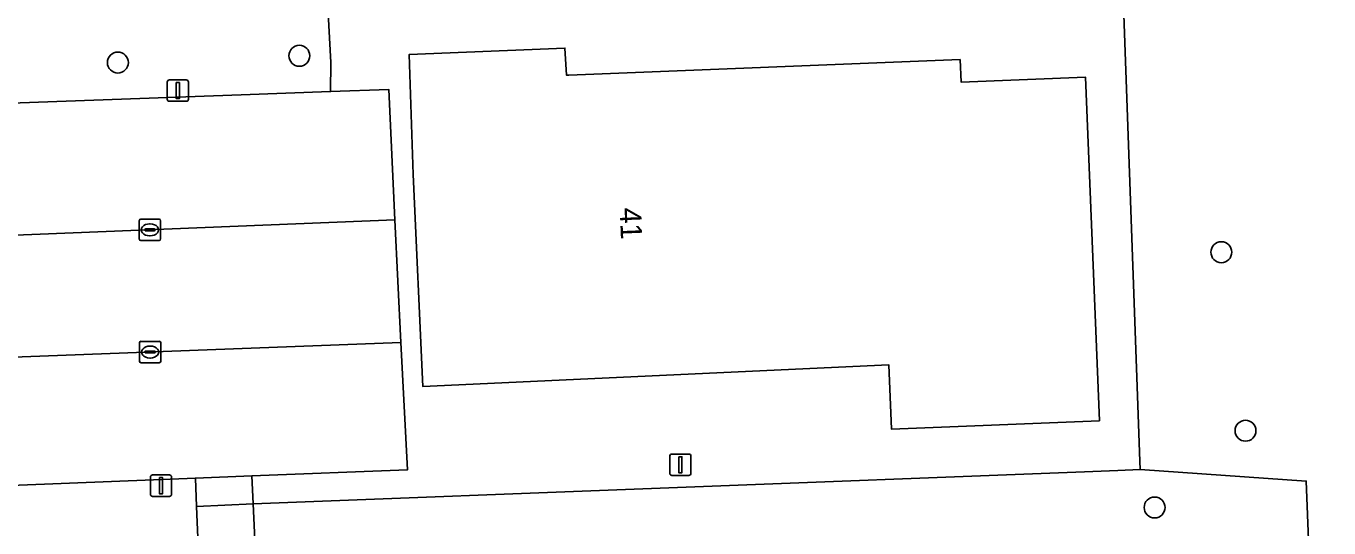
# Model space of a CAD drawing. Extents: x 162510 to 163918, y 388494 to 389774.
# Drawn here: x 162603.2 to 162664.2, y 388722 to 388745.4 of the extents above; entities that cross this region are included whole.
import ezdxf

# ---------------------------------------------------------------- set-up
doc = ezdxf.new("R2010")
doc.units = 0
for name, color, linetype in [('IMGEO_Boom', 7, 'Continuous'), ('IMGEO_Groenvoorziening', 7, 'Continuous'), ('IMGEO_Hek', 7, 'Continuous'), ('IMGEO_Kolk', 7, 'Continuous'), ('IMGEO_Lichtmast', 7, 'Continuous'), ('IMGEO_Pand', 7, 'Continuous'), ('IMGEO_Pand_nummerreeks', 7, 'Continuous'), ('IMGEO_Parkeervlak_open', 7, 'Continuous'), ('IMGEO_Voetpad_open', 7, 'Continuous')]:
    doc.layers.add(name, color=color, linetype=linetype)

msp = doc.modelspace()

# ---------------------------------------------------------------- linework, layer by layer
at = {"layer": 'IMGEO_Boom'}
for centre in [(162607.538, 388743.725), (162616.024, 388744.043), (162659.135, 388734.868), (162660.266, 388726.53), (162656.015, 388722.946)]:
    msp.add_circle(centre, 0.489, dxfattribs=at)
at = {"layer": 'IMGEO_Groenvoorziening'}
for points in [[(162570.603, 388903.112), (162575.652, 388750), (162576.205, 388733.677), (162576.423, 388733.739), (162576.634, 388733.821), (162576.837, 388733.921), (162577.03, 388734.039), (162577.212, 388734.174), (162577.381, 388734.324), (162577.536, 388734.489), (162577.66, 388734.646), (162577.999, 388735.283), (162577.741, 388740.923), (162577.5, 388746.093), (162578.716, 388746.131), (162579.502, 388746.156), (162579.691, 388740.996), (162613.301, 388742.225), (162617.482, 388742.368), (162617.493, 388743.727), (162617.26, 388748.066), (162576.503, 388746.666), (162571.458, 388901.227)], [(162672.289, 388823.443), (162675.321, 388750.649), (162654.434, 388749.809), (162654.518, 388747.72), (162655.329, 388725.102), (162655.344, 388724.714), (162663.108, 388724.176), (162663.228, 388721.043), (162672.068, 388721.393), (162672.037, 388721.095), (162692.862, 388721.935), (162693.526, 388721.762), (162693.788, 388721.694), (162698.73, 388720.407)]]:
    msp.add_lwpolyline(points, dxfattribs=at)
for points in [[(162611.219, 388722.999), (162611.166, 388724.317), (162578.56, 388723.023), (162578.31, 388727.925), (162577.395, 388728.281), (162576.389, 388728.377), (162577.766, 388721.486), (162578.525, 388717.688), (162578.613, 388717.246), (162578.636, 388716.894), (162581.582, 388716.929), (162584.933, 388716.929), (162611.423, 388717.95), (162611.381, 388718.989)], [(162655.344, 388724.714), (162654.289, 388724.673), (162652.74, 388724.613), (162613.863, 388723.119), (162614.044, 388719.095), (162652.876, 388720.633), (162654.987, 388720.717), (162663.228, 388721.043), (162663.108, 388724.176)]]:
    msp.add_lwpolyline(points, close=True, dxfattribs=at)
at = {"layer": 'IMGEO_Hek'}
for points in [[(162652.74, 388724.613), (162613.863, 388723.119)], [(162654.289, 388724.673), (162652.74, 388724.613)], [(162655.344, 388724.714), (162654.289, 388724.673)]]:
    msp.add_lwpolyline(points, dxfattribs=at)
at = {"layer": 'IMGEO_Kolk'}
for p, q in [((162608.536, 388735.485), (162608.536, 388736.337)), ((162608.611, 388736.411), (162609.463, 388736.411)), ((162609.024, 388736.191), (162609.049, 388736.191)), ((162609.537, 388736.337), (162609.537, 388735.485)), ((162608.795, 388735.905), (162608.795, 388735.917)), ((162609.233, 388735.868), (162608.835, 388735.868)), ((162608.838, 388735.954), (162609.236, 388735.954)), ((162609.047, 388735.631), (162609.022, 388735.631)), ((162609.279, 388735.917), (162609.279, 388735.905)), ((162609.463, 388735.411), (162608.611, 388735.411)), ((162608.621, 388730.705), (162609.473, 388730.705)), ((162608.546, 388729.779), (162608.546, 388730.631)), ((162608.805, 388730.199), (162608.805, 388730.211)), ((162609.243, 388730.162), (162608.845, 388730.162)), ((162608.848, 388730.248), (162609.246, 388730.248)), ((162609.034, 388730.485), (162609.059, 388730.485)), ((162609.289, 388730.211), (162609.289, 388730.199)), ((162609.547, 388730.631), (162609.547, 388729.779)), ((162609.473, 388729.705), (162608.621, 388729.705)), ((162609.057, 388729.925), (162609.032, 388729.925))]:
    msp.add_line(p, q, dxfattribs=at)
for points in [[(162608.536, 388735.485), (162608.536, 388736.337)], [(162608.611, 388736.411), (162609.463, 388736.411)], [(162609.537, 388736.337), (162609.537, 388735.485)], [(162609.463, 388735.411), (162608.611, 388735.411)], [(162608.621, 388730.705), (162609.473, 388730.705)], [(162608.546, 388729.779), (162608.546, 388730.631)], [(162609.547, 388730.631), (162609.547, 388729.779)], [(162609.473, 388729.705), (162608.621, 388729.705)]]:
    msp.add_lwpolyline(points, dxfattribs=at)
for centre, radius, start, end in [((162608.613, 388736.335), 0.0765, 91.55205, 178.44795), ((162608.613, 388736.335), 0.0765, 91.55205, 178.44795), ((162609.461, 388736.335), 0.0765, 1.55205, 88.44795), ((162609.461, 388736.335), 0.0765, 1.55205, 88.44795), ((162608.835, 388735.914), 0.0403, 85.87752, 175.75265), ((162608.832, 388735.904), 0.0366, 178.93798, 274.71019), ((162609.236, 388735.911), 0.043, 264.86636, 352.45326), ((162609.24, 388735.916), 0.0386, 1.73085, 96.63898), ((162608.613, 388735.487), 0.0765, 181.55205, 268.44795), ((162608.613, 388735.487), 0.0765, 181.55205, 268.44795), ((162609.461, 388735.487), 0.0765, 271.55205, 358.44795), ((162609.461, 388735.487), 0.0765, 271.55205, 358.44795), ((162608.623, 388730.629), 0.0765, 91.55205, 178.44795), ((162608.623, 388730.629), 0.0765, 91.55205, 178.44795), ((162609.471, 388730.629), 0.0765, 1.55205, 88.44795), ((162609.471, 388730.629), 0.0765, 1.55205, 88.44795), ((162608.845, 388730.208), 0.0403, 85.87752, 175.75265), ((162608.842, 388730.198), 0.0366, 178.93798, 274.71019), ((162609.246, 388730.205), 0.043, 264.86636, 352.45326), ((162609.25, 388730.21), 0.0386, 1.73085, 96.63898), ((162608.623, 388729.781), 0.0765, 181.55205, 268.44795), ((162608.623, 388729.781), 0.0765, 181.55205, 268.44795), ((162609.471, 388729.781), 0.0765, 271.55205, 358.44795), ((162609.471, 388729.781), 0.0765, 271.55205, 358.44795)]:
    msp.add_arc(centre, radius, start, end, dxfattribs=at)
for centre, major_axis, ratio, start_param, end_param in [((162609.023, 388735.911), (-0.387, 0.002), 0.722429, 4.712389, 7.853982), ((162609.048, 388735.911), (-0.39, 0.002), 0.717154, 1.570796, 4.712389), ((162609.033, 388730.205), (-0.387, 0.002), 0.722429, 4.712389, 7.853982), ((162609.058, 388730.205), (-0.39, 0.002), 0.717154, 1.570796, 4.712389)]:
    msp.add_ellipse(centre, major_axis=major_axis, ratio=ratio, start_param=start_param, end_param=end_param, dxfattribs=at)
at = {"layer": 'IMGEO_Lichtmast'}
for p, q in [((162609.945, 388742.915), (162610.735, 388742.915)), ((162610.735, 388742.915), (162609.945, 388742.915)), ((162609.845, 388742.015), (162609.845, 388742.815)), ((162609.845, 388742.815), (162609.845, 388742.015)), ((162610.835, 388742.815), (162610.835, 388742.015)), ((162610.835, 388742.015), (162610.835, 388742.815)), ((162610.735, 388741.915), (162609.945, 388741.915)), ((162609.945, 388741.915), (162610.735, 388741.915)), ((162633.345, 388724.542), (162633.345, 388725.342)), ((162633.345, 388725.342), (162633.345, 388724.542)), ((162633.445, 388725.442), (162634.235, 388725.442)), ((162634.235, 388725.442), (162633.445, 388725.442)), ((162634.335, 388725.342), (162634.335, 388724.542)), ((162634.335, 388724.542), (162634.335, 388725.342)), ((162609.061, 388723.564), (162609.061, 388724.364)), ((162609.061, 388724.364), (162609.061, 388723.564)), ((162609.161, 388724.464), (162609.951, 388724.464)), ((162609.951, 388724.464), (162609.161, 388724.464)), ((162610.051, 388724.364), (162610.051, 388723.564)), ((162610.051, 388723.564), (162610.051, 388724.364)), ((162634.235, 388724.442), (162633.445, 388724.442)), ((162633.445, 388724.442), (162634.235, 388724.442)), ((162609.951, 388723.464), (162609.161, 388723.464)), ((162609.161, 388723.464), (162609.951, 388723.464))]:
    msp.add_line(p, q, dxfattribs=at)
for points in [[(162610.265, 388742.79), (162610.415, 388742.79), (162610.415, 388742.04), (162610.265, 388742.04), (162610.265, 388742.79)], [(162633.765, 388725.317), (162633.915, 388725.317), (162633.915, 388724.567), (162633.765, 388724.567), (162633.765, 388725.317)], [(162609.481, 388724.339), (162609.631, 388724.339), (162609.631, 388723.589), (162609.481, 388723.589), (162609.481, 388724.339)]]:
    msp.add_lwpolyline(points, dxfattribs=at)
for centre, start, end in [((162609.945, 388742.815), 90, 180), ((162609.945, 388742.815), 90, 180), ((162610.735, 388742.815), 0, 90), ((162610.735, 388742.815), 360, 90), ((162609.945, 388742.015), 180, 270), ((162609.945, 388742.015), 180, 270), ((162610.735, 388742.015), 270, 0), ((162610.735, 388742.015), 270, 0), ((162633.445, 388725.342), 90, 180), ((162633.445, 388725.342), 90, 180), ((162634.235, 388725.342), 0, 90), ((162634.235, 388725.342), 360, 90), ((162609.161, 388724.364), 90, 180), ((162609.161, 388724.364), 90, 180), ((162609.951, 388724.364), 0, 90), ((162609.951, 388724.364), 360, 90), ((162633.445, 388724.542), 180, 270), ((162633.445, 388724.542), 180, 270), ((162634.235, 388724.542), 270, 0), ((162634.235, 388724.542), 270, 0), ((162609.161, 388723.564), 180, 270), ((162609.161, 388723.564), 180, 270), ((162609.951, 388723.564), 270, 0), ((162609.951, 388723.564), 270, 0)]:
    msp.add_arc(centre, 0.1, start, end, dxfattribs=at)
at = {"layer": 'IMGEO_Pand'}
msp.add_lwpolyline([(162646.92, 388743.867), (162628.632, 388743.136), (162628.518, 388743.131), (162628.439, 388744.399), (162621.162, 388744.102), (162621.353, 388738.494), (162621.796, 388728.603), (162643.587, 388729.613), (162643.707, 388726.604), (162653.435, 388726.995), (162652.778, 388743.049), (162646.964, 388742.816)], close=True, dxfattribs=at)
at = {"layer": 'IMGEO_Parkeervlak_open'}
for points in [[(162620.203, 388742.474), (162617.482, 388742.368), (162613.301, 388742.225), (162579.691, 388740.996), (162577.741, 388740.923), (162577.999, 388735.283), (162577.66, 388734.646), (162620.485, 388736.373)], [(162576.389, 388728.377), (162577.395, 388728.281), (162578.31, 388727.925), (162578.345, 388729.041), (162620.774, 388730.652), (162620.485, 388736.373), (162577.66, 388734.646), (162577.536, 388734.489), (162577.381, 388734.324), (162577.212, 388734.174), (162577.03, 388734.039), (162576.837, 388733.921), (162576.634, 388733.821), (162576.423, 388733.739), (162576.205, 388733.677)], [(162611.166, 388724.317), (162613.805, 388724.422), (162621.083, 388724.711), (162620.774, 388730.652), (162578.345, 388729.041), (162578.31, 388727.925), (162578.56, 388723.023)]]:
    msp.add_lwpolyline(points, close=True, dxfattribs=at)
at = {"layer": 'IMGEO_Voetpad_open'}
for points in [[(162654.518, 388747.72), (162654.434, 388749.809), (162654.349, 388750.726), (162617.198, 388749.222), (162617.249, 388748.279), (162617.26, 388748.066), (162617.493, 388743.727), (162617.482, 388742.368), (162620.203, 388742.474), (162620.485, 388736.373), (162620.774, 388730.652), (162621.083, 388724.711), (162613.805, 388724.422), (162613.863, 388723.119), (162652.74, 388724.613), (162654.289, 388724.673), (162655.344, 388724.714), (162655.329, 388725.102)], [(162653.435, 388726.995), (162643.707, 388726.604), (162643.587, 388729.613), (162621.796, 388728.603), (162621.353, 388738.494), (162621.162, 388744.102), (162628.439, 388744.399), (162628.518, 388743.131), (162628.632, 388743.136), (162646.92, 388743.867), (162646.964, 388742.816), (162652.778, 388743.049)], [(162613.805, 388724.422), (162611.166, 388724.317), (162611.219, 388722.999), (162613.863, 388723.119)]]:
    msp.add_lwpolyline(points, close=True, dxfattribs=at)
msp.add_lwpolyline([(162616.068, 388673.878), (162615.501, 388686.546), (162614.712, 388704.165), (162614.13, 388717.165), (162614.09, 388718.064), (162614.044, 388719.095), (162613.863, 388723.119), (162611.219, 388722.999), (162611.381, 388718.989), (162611.423, 388717.95), (162611.441, 388717.506), (162611.458, 388717.081), (162611.459, 388717.051), (162611.976, 388704.282), (162612.333, 388695.447), (162612.698, 388686.433), (162613.211, 388673.725)], dxfattribs=at)

# ---------------------------------------------------------------- texts
at = {"layer": 'IMGEO_Pand_nummerreeks'}
msp.add_text('41', height=1, rotation=272.30253, dxfattribs=at).set_placement((162631.003, 388736.933))

doc.saveas('drawing.dxf')
